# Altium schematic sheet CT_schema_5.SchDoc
size 297 x 271 mm
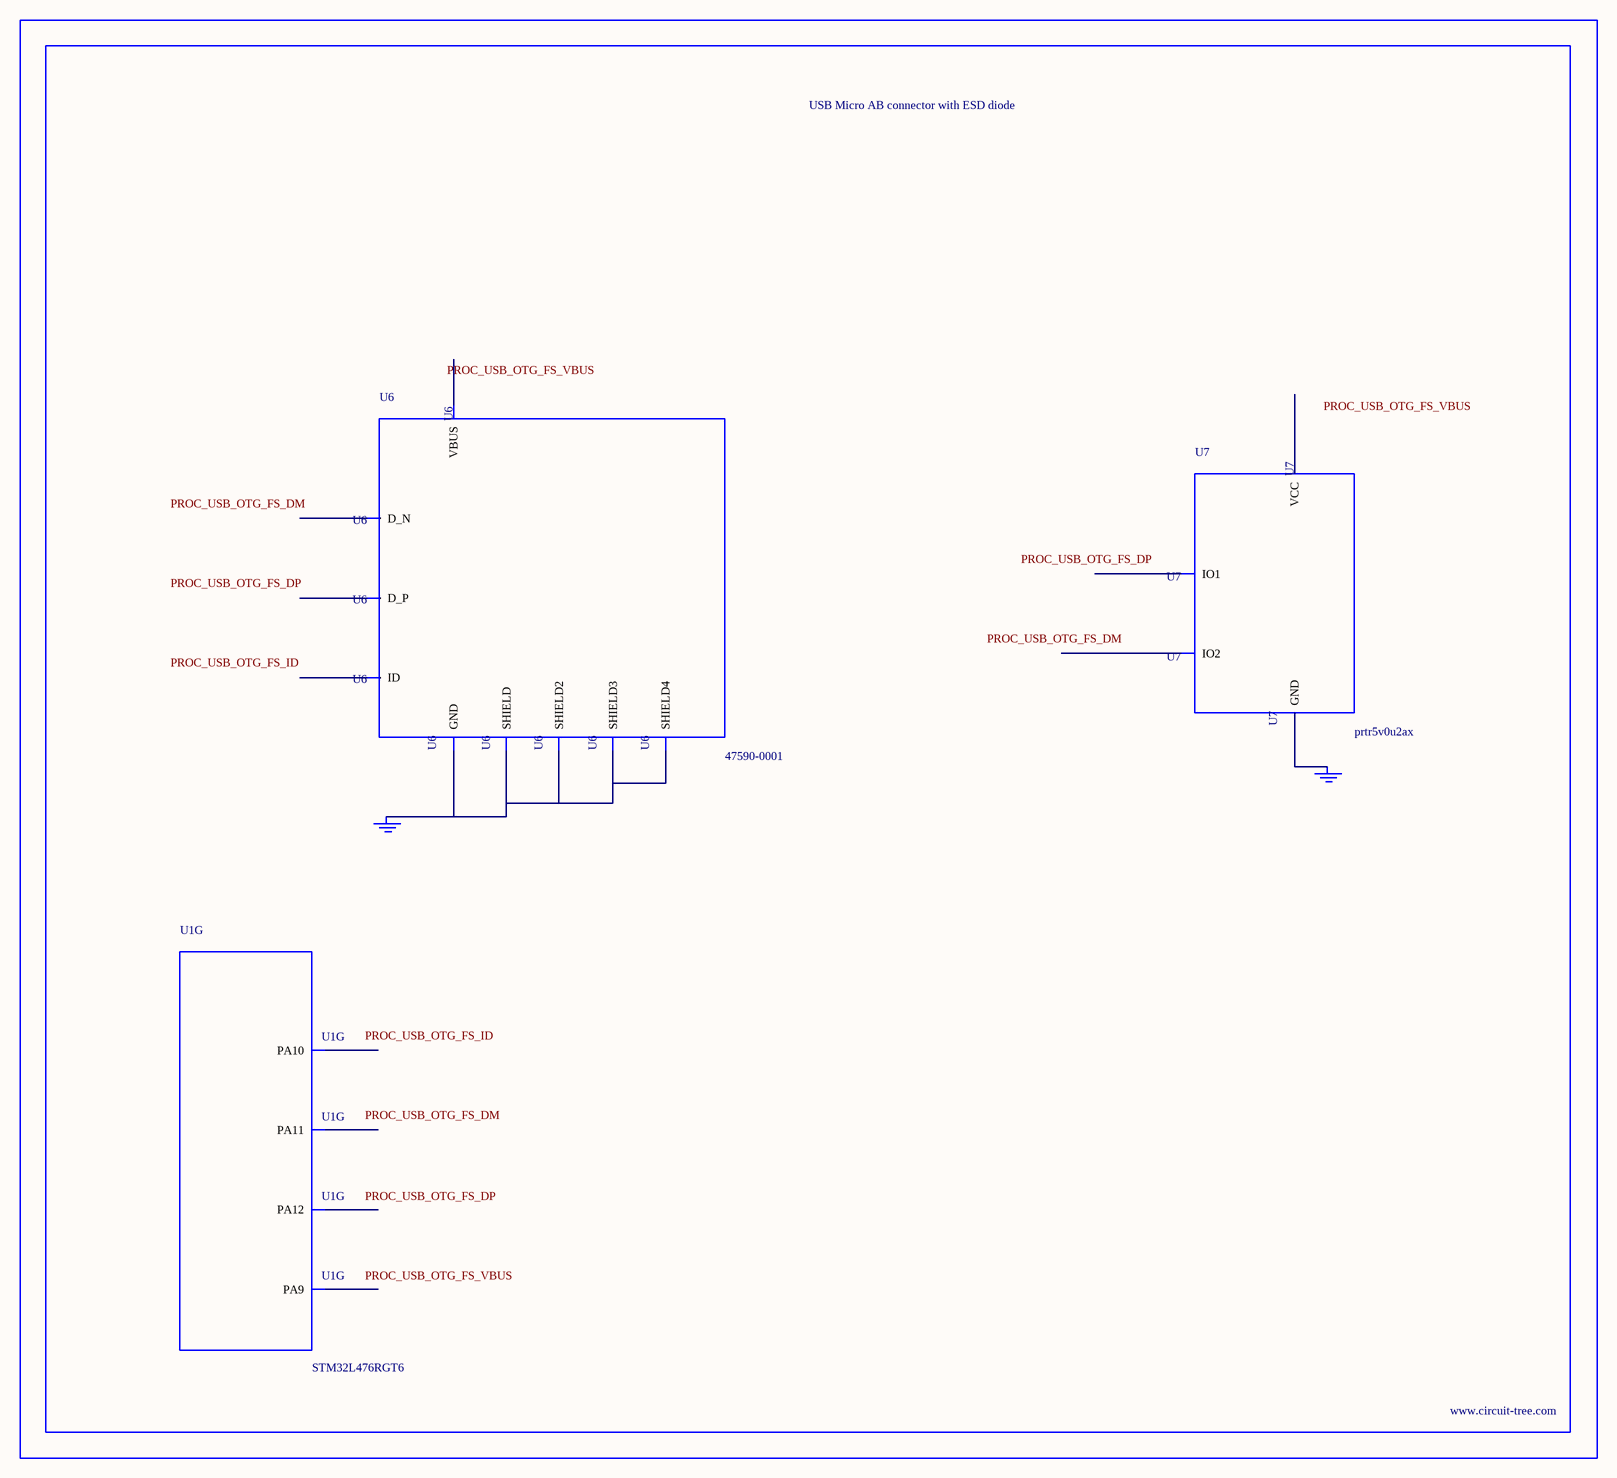
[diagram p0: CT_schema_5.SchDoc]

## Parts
BORDER4  (no value)
GND_INSTANCE_4_0  (no value)
GND_INSTANCE_4_1  (no value)
U1  STM32L476RGT6  [LQFP64]  (part G of 8)
U6  47590-0001  [MICRO_USB_AB]
U7  prtr5v0u2ax  [SOT143B]

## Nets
NetGND_INSTANCE_4_0_0: GND_INSTANCE_4_0.0(GND) U6.5(GND) U6.6(SHIELD) U6.7(SHIELD2) U6.8(SHIELD3) U6.9(SHIELD4)
NetGND_INSTANCE_4_1_0: GND_INSTANCE_4_1.0(GND) U7.1(GND)

Not connected (* = marked no-connect by the designer): U1 42(PA9) 43(PA10) 44(PA11) 45(PA12); U6 1(VBUS) 2(D_N) 3(D_P) 4(ID); U7 2(IO1) 3(IO2) 4(VCC)

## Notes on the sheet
- Labels drawn without touching a wire or pin: PROC_USB_OTG_FS_DM, PROC_USB_OTG_FS_DP, PROC_USB_OTG_FS_ID, PROC_USB_OTG_FS_VBUS

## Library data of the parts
BORDER4 = BORDER_PAGE4
GND_INSTANCE_4_0 GND_INSTANCE_4_1 = GND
